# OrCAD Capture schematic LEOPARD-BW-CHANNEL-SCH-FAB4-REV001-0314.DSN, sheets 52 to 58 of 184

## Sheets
52 137_CPLD FOR LOGIC: size A3; title: CPLD FOR LOGIC
53 136_POWER CONNECTOR: size A3; title: POWER CONNECTOR
54 135_IRQ_ALERT: size A3; title: IRQ_ALERT
55 134_CKMNG 202: size A3; title: CKMNG 202
56 133_DB1900Z CLOCK TERMINATION2: size A3; title: DB1900Z CLOCK TERMINATION2
57 132_DB1900Z CLOCK TERMINATION1: size A3; title: DB1900Z CLOCK TERMINATION1
58 131_DB1900Z CLOCK BUFFER: size A3; title: DB1900Z CLOCK BUFFER

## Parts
sheet 131_DB1900Z CLOCK BUFFER
C433  SC10U6D3V5KX-4GP  [C805H58]
C434  SCD1U16V2KX-3GP  [C402H22]
C435  SCD1U16V2KX-3GP  [C402H22]
C436  SC10U6D3V5KX-4GP  [C805H58]
C437  SC10U6D3V5KX-4GP  [C805H58]
C438  SCD1U16V2KX-3GP  [C402H22]
C439  SCD1U16V2KX-3GP  [C402H22]
C440  SCD1U16V2KX-3GP  [C402H22]
C441  SCD1U16V2KX-3GP  [C402H22]
C442  SCD1U16V2KX-3GP  [C402H22]
C443  SCD1U16V2KX-3GP  [C402H22]
C444  SCD1U16V2KX-3GP  [C402H22]
C445  SCD1U16V2KX-3GP  [C402H22]
C446  SCD1U16V2KX-3GP  [C402H22]
C447  SCD1U16V2KX-3GP  [C402H22]
C448  SCD1U16V2KX-3GP  [C402H22]
C449  SCD1U16V2KX-3GP  [C402H22]
DB1  9ZX21901BKLFT-GP-U  [QFN72-G6D15-DIFF-H40]
L16  MMZ2012S601ATA1N-GP  [L805H42]
L17  BLM18SG331TN1D-GP  [L1608-UH38]
Q5  2N7002-7F-GP  [SOT23DGS2D4H44]
R442  2D2R3J-2-GP  [R603H22]
R443  1KR2F-3-GP  [R402H16]
R444  1KR2F-3-GP  [R402H16]
R445  1KR2F-L-GP  [R402H16]
R446  1KR2F-L-GP  [R402H16]
R447  2D2R3J-2-GP  [R603H22]
R448  412R2F-GP  [R402H16]
R449  4K7R2J-2-GP  [R402H16]
R450  4K7R2J-2-GP  [R402H16]
R451  4K7R2J-2-GP  [R402H16]
R452  4K7R2J-2-GP  [R402H16]
R453  4K7R2J-2-GP  [R402H16]
R454  4K7R2J-2-GP  [R402H16]
R455  0R2J-2-GP  [R402H16]
R456  4K7R2J-2-GP  [R402H16]
R457  27D4R2F-3-GP  [R402H16]
R458  27D4R2F-3-GP  [R402H16]
R459  42D2R2F-GP  [R402H16]
R460  42D2R2F-GP  [R402H16]
R496  4K7R2J-2-GP  [R402H16]
R498  4K7R2J-2-GP  [R402H16]
R653  0R2J-2-GP  [R402H16]
R1120  1KR2F-3-GP  [R402H16]
sheet 132_DB1900Z CLOCK TERMINATION1
R469  27D4R2F-3-GP  [R402H16]
R471  42D2R2F-GP  [R402H16]
R472  27D4R2F-3-GP  [R402H16]
R473  27D4R2F-3-GP  [R402H16]
R474  42D2R2F-GP  [R402H16]
R475  42D2R2F-GP  [R402H16]
R476  27D4R2F-3-GP  [R402H16]
R477  27D4R2F-3-GP  [R402H16]
R479  42D2R2F-GP  [R402H16]
R481  27D4R2F-3-GP  [R402H16]
R483  42D2R2F-GP  [R402H16]
R486  27D4R2F-3-GP  [R402H16]
R488  42D2R2F-GP  [R402H16]
R490  27D4R2F-3-GP  [R402H16]
R492  42D2R2F-GP  [R402H16]
R493  42D2R2F-GP  [R402H16]
R535  42D2R2F-GP  [R402H16]
R537  27D4R2F-3-GP  [R402H16]
R539  42D2R2F-GP  [R402H16]
R546  27D4R2F-3-GP  [R402H16]
R703  42D2R2F-GP  [R402H16]
R704  27D4R2F-3-GP  [R402H16]
R705  27D4R2F-3-GP  [R402H16]
R739  42D2R2F-GP  [R402H16]
sheet 133_DB1900Z CLOCK TERMINATION2
R501  27D4R2F-3-GP  [R402H16]
R502  27D4R2F-3-GP  [R402H16]
R503  42D2R2F-GP  [R402H16]
R504  42D2R2F-GP  [R402H16]
R505  27D4R2F-3-GP  [R402H16]
R506  27D4R2F-3-GP  [R402H16]
R507  42D2R2F-GP  [R402H16]
R508  42D2R2F-GP  [R402H16]
R510  27D4R2F-3-GP  [R402H16]
R512  42D2R2F-GP  [R402H16]
R514  27D4R2F-3-GP  [R402H16]
R516  42D2R2F-GP  [R402H16]
R517  27D4R2F-3-GP  [R402H16]
R519  42D2R2F-GP  [R402H16]
R521  27D4R2F-3-GP  [R402H16]
R523  42D2R2F-GP  [R402H16]
R525  27D4R2F-3-GP  [R402H16]
R527  42D2R2F-GP  [R402H16]
R529  27D4R2F-3-GP  [R402H16]
R531  42D2R2F-GP  [R402H16]
R735  42D2R2F-GP  [R402H16]
R736  42D2R2F-GP  [R402H16]
R737  27D4R2F-3-GP  [R402H16]
R738  27D4R2F-3-GP  [R402H16]
R758  42D2R2F-GP  [R402H16]
R759  27D4R2F-3-GP  [R402H16]
R760  42D2R2F-GP  [R402H16]
R761  27D4R2F-3-GP  [R402H16]
sheet 134_CKMNG 202
C452  SCD01U25V2KX-3GP  [C402H22]
C453  SC10U6D3V5KX-4GP  [C805H58]
C454  SC1U10V2KX-4-GP  [C402H22]
C455  SCD01U25V2KX-3GP  [C402H22]
C456  SCD1U16V2KX-3GP  [C402H22]
C457  SC1U10V2KX-4-GP  [C402H22]
C458  SCD1U16V2KX-3GP  [C402H22]
C459  SCD1U16V2KX-3GP  [C402H22]
C460  SC1U10V2KX-4-GP  [C402H22]
C461  SC1U10V2KX-4-GP  [C402H22]
C462  SC12P50V2JN-3GP  [C402H24]
C463  SC12P50V2JN-3GP  [C402H24]
L18  MMZ2012S601ATA1N-GP  [L805H42]
R201  33R2F-3-GP  [R402H16]
R541  2D2R3-1-U-GP  [R603H22]
R542  2D2R3-1-U-GP  [R603H22]
R543  4K7R2F-GP  [R402H16]
R544  4K7R2F-GP  [R402H16]
R545  4K7R2F-GP  [R402H16]
R548  22R2F-1-GP  [R402H16]
R549  1KR2F-3-GP  [R402H16]
R550  475R2F-L1-GP  [R402H16]
R551  100R2F-L1-GP-U  [R402H14]
R591  22R2F-1-GP  [R402H16]
R592  22R2F-1-GP  [R402H16]
R734  22R2F-1-GP  [R402H16]
TP299  TPAD24  [TPAD24]
TP300  TPAD24  [TPAD24]
TP439  TPAD24  [TPAD24]
U35  ICS9FGP202YKLF-GP  [QFN40-G3H40]
X5  XTAL-25MHZ-96GP  [SMD49-4H56]
sheet 135_IRQ_ALERT
C479  SCD1U16V2KX-3GP  [C402H22]
Q82  2N7002-7F-GP  [SOT23DGS2D4H44]
R804  10KR2J-3-GP  [R402H16]
R805  1KR2F-L-GP  [R402H16]
R818  0R2J-2-GP  [R402H16]
R819  1KR2F-3-GP  [R402H16]
R820  0R2J-2-GP  [R402H16]
R821  0R2J-2-GP  [R402H16]
R937  10KR2J-3-GP  [R402H16]
R1854  0R2J-2-GP  [R402H16]
sheet 136_POWER CONNECTOR
PWRCN1  TE-CONN12-2R-2-GP  [PREFIT-12P-104170H319]
PWRCN2  TE-CONN12-2R-2-GP  [PREFIT-12P-104170H319]
sheet 137_CPLD FOR LOGIC
C109  SCD1U16V2KX-3GP  [C402H22]
C405  SC1U10V2KX-4-GP  [C402H22]
C410  SC1U10V2KX-4-GP  [C402H22]
C415  SC1U10V2KX-4-GP  [C402H22]
C416  SC1U10V2KX-4-GP  [C402H22]
C417  SC1U10V2KX-4-GP  [C402H22]
C418  SC1U10V2KX-4-GP  [C402H22]
C420  SC1U10V2KX-4-GP  [C402H22]
C421  SC1U10V2KX-4-GP  [C402H22]
C422  SC1U10V2KX-4-GP  [C402H22]
C423  SC1U10V2KX-4-GP  [C402H22]
CPLD2  LCMXO256C-3MN100C-GP  [BGA100G80H54]
Q50  2N7002-7F-GP  [SOT23DGS2D4H44]
R276  100KR2F-L1-GP  [R402H16]
R388  0R2J-2-GP  [R402H16]
R405  0R2J-2-GP  [R402H16]
R424  0R2J-2-GP  [R402H16]
R430  0R2J-2-GP  [R402H16]
R433  0R2J-2-GP  [R402H16]
R435  49D9R2F-GP  [R402H16]
R436  49D9R2F-GP  [R402H16]
R437  49D9R2F-GP  [R402H16]
R438  49D9R2F-GP  [R402H16]
R439  49D9R2F-GP  [R402H16]
R441  49D9R2F-GP  [R402H16]
R461  0R2J-2-GP  [R402H16]
R485  49D9R2F-GP  [R402H16]
R495  0R2J-2-GP  [R402H16]
R497  0R2J-2-GP  [R402H16]
R513  0R2J-2-GP  [R402H16]
R526  0R2J-2-GP  [R402H16]
R534  0R2J-2-GP  [R402H16]
R536  0R2J-2-GP  [R402H16]
R607  0R2J-2-GP  [R402H16]
R613  0R2J-2-GP  [R402H16]
R642  1KR2F-3-GP  [R402H16]
R643  1KR2F-3-GP  [R402H16]
R644  10KR2F-2-GP  [R402H16]
R647  0R2J-2-GP  [R402H16]
R652  0R2J-2-GP  [R402H16]
R658  10KR2F-2-GP  [R402H16]
R659  1KR2F-3-GP  [R402H16]
R664  0R2J-2-GP  [R402H16]
R666  10KR2F-2-GP  [R402H16]
R667  4K7R2F-GP  [R402H16]
R668  10KR2J-3-GP  [R402H16]
R669  4K75R2F-1-GP  [R402H16]
R670  0R2J-2-GP  [R402H16]
R671  10KR2J-3-GP  [R402H16]
R672  10KR2J-3-GP  [R402H16]
R673  10KR2J-3-GP  [R402H16]
R686  0R2J-2-GP  [R402H16]
R688  0R2J-2-GP  [R402H16]
R770  1KR2J-1-GP  [R402H16]
R861  49D9R2F-GP  [R402H16]
R871  49D9R2F-GP  [R402H16]
R885  49D9R2F-GP  [R402H16]
R886  49D9R2F-GP  [R402H16]
R908  49D9R2F-GP  [R402H16]
R928  49D9R2F-GP  [R402H16]
R1215  49D9R2F-GP  [R402H16]
R1223  49D9R2F-GP  [R402H16]
R1224  49D9R2F-GP  [R402H16]
U24  SN74LVC1G07DCKRG4-2-GP  [SC70-5H44]

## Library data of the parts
C433 C436 C437 C453 = SC10U6D3V5KX-4GP: CHIP CAP C 10U 6.3V K0805 X7R; GREENDFACTOR: R2_SA;HF_SA;G_SA;; Part Number: 78.10620.21L; Part Type: SMD-BCG; SPEC: http://wpqssvr.wistron.com.tw:7001/wpqs/servlet/COM.qpart.Attachment?PartNumber=78.10620.21L
C434 C435 C438-C449 = SCD1U16V2KX-3GP: CHIP CAP C 0.1U 16V K0402 X7R; Category: CLK GEN; GREENDFACTOR: R_SA;HF_SA;G_SA;; Part Number: 78.10421.2FL; Quotation: 12_14; Type: SMD
DB1 = 9ZX21901BKLFT-GP-U: IC BUF 9ZX21901BKLFT MLF 72P; GREENDFACTOR: R2_SA;HF_SA;; Part Number: 71.92190.003; Part Type: ASIC-G2; SPEC: http://wpqssvr.wistron.com.tw:7001/wpqs/servlet/COM.qpart.Attachment?PartNumber=71.92190.003
L16 L18 = MMZ2012S601ATA1N-GP: CHIP BEAD MMZ2012S601ATA1N TDK; Category: Clock; DESCRIPTIO: CHIP BEAD MMZ2012S601ATA1N TDK; GREENDFACTOR: R2_SA;; Package Type: DISCRET-G5; Part Number: 68.00109.171; Part Type: DISCRET-G5; SPEC: http://wpqssvr.wistron.com.tw:7001/wpqs/servlet/COM.qpart.Attachment?PartNumber=68.00109.171; VENDORPARTNUMBER: MMZ2012S601ATA1N
L17 = BLM18SG331TN1D-GP: CHIP BEAD BLM18SG331TN1D; GREENDFACTOR: R2_SA;; Package Type: DISCRET-G2; Part Number: 68.00143.151; SPEC: http://wpqssvr.wistron.com.tw:7001/wpqs/servlet/COM.qpart.Attachment?PartNumber=68.00143.151
Q5 Q50 Q82 = 2N7002-7F-GP: FET MOS 2N7002-7-F NC SOT-23; GREENDFACTOR: R2_SA;HF_SA;G_SA;; Part Number: 84.27002.N31; Part Type: DISCRET-G; SPEC: http://wpqssvr.wistron.com.tw:7001/wpqs/servlet/COM.qpart.Attachment?PartNumber=84.27002.N31
R442 R447 = 2D2R3J-2-GP: CHIP RES 2.2 J 1/10W 0603; GREENDFACTOR: R2_SA;HF_SA;G_SA;; Package Type: SMD-RG; Part Number: 63.2R233.15L; SPEC: http://wpqssvr.wistron.com.tw:7001/wpqs/servlet/COM.qpart.Attachment?PartNumber=63.2R233.15L
R443 R444 = 1KR2F-3-GP: CHIP RES 1K F 1/16W 0402; Category: PCH; GREENDFACTOR: R2_SA;HF_SA;G_SA;; POP?: NOPOP; Package Type: SMD-RG; Part Number: 64.10015.6DL; Part Type: SMD-RG; SPEC: http://wpqssvr.wistron.com.tw:7001/wpqs/servlet/COM.qpart.Attachment?PartNumber=64.10015.6DL; VENDORPARTNUMBER: RM04FTN1001 / RTT021001FTH / RR0510S-1001-FN / RC0402FR-071KL/WR04X1001FTL
R445 R446 = 1KR2F-L-GP: CHIP RES 1K F 1/16W 0402; GREENDFACTOR: R2_SA;HF_SA;G_SA;; Package Type: SMD-RG2; Part Number: 64.10015.L1L; SPEC: http://wpqssvr.wistron.com.tw:7001/wpqs/servlet/COM.qpart.Attachment?PartNumber=64.10015.L1L
R448 = 412R2F-GP: CHIP RES 412 F 1/16W 0402; Category: Clock; DESCRIPTIO: CHIP RES 412 F 1/16W 0402; GREENDFACTOR: R2_SA;HF_SA;G_SA;; Package Type: RCL_GP; Part Number: 64.41205.6DL; Part Type: RCL_GP; SPEC: http://wpqssvr.wistron.com.tw:7001/wpqs/servlet/COM.qpart.Attachment?PartNumber=64.41205.6DL; VENDORPARTNUMBER: RM04FTN4120/RTT024120FTH/RR0510S-4120-FN/RC0402FR-07412RL
R449 R452 = 4K7R2J-2-GP: CHIP RES 4.7K J 1/16W 0402; Category: SMBUS; GREENDFACTOR: R_SA;HF_SA;G_SA;; POP?: NOPOP; Part Number: 63.47234.1DL; Quotation: 8_1; Type: SMD
R450 R451 R453 R454 R456 R496 R498 = 4K7R2J-2-GP: CHIP RES 4.7K J 1/16W 0402; Category: SMBUS; GREENDFACTOR: R_SA;HF_SA;G_SA;; Part Number: 63.47234.1DL; Quotation: 8_1; Type: SMD
R455 = 0R2J-2-GP: CHIP RES 0 J 1/16W 0402; Category: PCH; DESCRIPTIO: CHIP RES 0 J 1/16W 0402; GREENDFACTOR: R2_SA;HF_SA;G_SA;; Package Type: SMD-RG; Part Number: 63.R0034.1DL; Part Type: SMD-RG; SPEC: http://wpqssvr.wistron.com.tw:7001/wpqs/servlet/COM.qpart.Attachment?PartNumber=63.R0034.1DL; VENDORPARTNUMBER: RM04JTN0/RTT02000JTH/RR0510X-000-XN/RC0402JR-070RL/WR04X000 PTL
R457 R458 R469 R472 R473 R476 R477 R481 R486 R490 R501 R502 R505 R506 R510 R514 R517 R521 R525 R529 R537 R546 R704 R705 R737 R738 R759 R761 = 27D4R2F-3-GP: CHIP RES 27.4 F 1/16W 0402; GREENDFACTOR: R2_SA;HF_SA;G_SA;; Part Number: 64.27R45.6DL; Part Type: SMD-RG2; SPEC: http://wpqssvr.wistron.com.tw:7001/wpqs/servlet/COM.qpart.Attachment?PartNumber=64.27R45.6DL
R459 R460 R471 R474 R475 R479 R483 R488 R492 R493 R503 R504 R507 R508 R512 R516 R519 R523 R527 R531 R535 R539 R703 R735 R736 R739 R758 R760 = 42D2R2F-GP: CHIP RES 42.2 F 1/16W 0402; Category: CLOCKS; Change to: 78P0751AA; GREENDFACTOR: R2_SA;HF_SA;G_SA;; Part Number: 64.42R25.6DL; Part Type: RCL_GP; SPEC: http://wpqssvr.wistron.com.tw:7001/wpqs/servlet/COM.qpart.Attachment?PartNumber=64.42R25.6DL; Vender: TA-I/RALEC/CYNTEC/YAGEO
R653 = 0R2J-2-GP: CHIP RES 0 J 1/16W 0402; Category: LOM - i350; DESCRIPTIO: CHIP RES 0 J 1/16W 0402; GREENDFACTOR: R2_SA;HF_SA;G_SA;; Package Type: SMD-RG; Part Number: 63.R0034.1DL; Part Type: SMD-RG; SPEC: http://wpqssvr.wistron.com.tw:7001/wpqs/servlet/COM.qpart.Attachment?PartNumber=63.R0034.1DL; VENDORPARTNUMBER: RM04JTN0/RTT02000JTH/RR0510X-000-XN/RC0402JR-070RL/WR04X000 PTL
R1120 = 1KR2F-3-GP: CHIP RES 1K F 1/16W 0402; GREENDFACTOR: R2_SA;HF_SA;G_SA;; POP?: NOPOP; Part Number: 64.10015.6DL; Part Type: SMD-RG; SPEC: http://wpqssvr.wistron.com.tw:7001/wpqs/servlet/COM.qpart.Attachment?PartNumber=64.10015.6DL
C452 C455 = SCD01U25V2KX-3GP: CHIP 0.01U 25V K0402 X7R(ROHS); Category: Clock; DESCRIPTIO: CHIP 0.01U 25V K0402 X7R(ROHS); GREENDFACTOR: R2_SA;HF_SA;G_SA;; Package Type: SMD-BCG; Part Number: 78.10322.2FL; Part Type: SMD-BCG; SPEC: http://wpqssvr.wistron.com.tw:7001/wpqs/servlet/COM.qpart.Attachment?PartNumber=78.10322.2FL; VENDORPARTNUMBER: 04023C103KAT2A/C1005X7R103KFT/GRM155R71E103KA01D/223891715636/CL05B103KA5NNNC/TMK105BJ103KV-F/C1005X7R1E103KT000F
C405 C410 C415-C418 C420-C423 C454 C457 C460 C461 = SC1U10V2KX-4-GP: CHIP CAP C 1U 10V K 0402 X6S; GREENDFACTOR: R2_SA;HF_SA;; Part Number: 78.10523.8FL; Part Type: SMD-BCG6; SPEC: http://wpqssvr.wistron.com.tw:7001/wpqs/servlet/COM.qpart.Attachment?PartNumber=78.10523.8FL
C456 C458 C459 = SCD1U16V2KX-3GP: CHIP CAP C 0.1U 16V K0402 X7R; CATEGORIES: CAP_1.xV; GREENDFACTOR: R2_SA;HF_SA;G_SA;; MAIN_SOURCE: M; Part Number: 78.10421.2FL; Part Type: SMD-BCG; SPEC: http://wpqssvr.wistron.com.tw:7001/wpqs/servlet/COM.qpart.Attachment?PartNumber=78.10421.2FL
C462 C463 = SC12P50V2JN-3GP: CHIP CAP C 12P 50V J0402 NPO; CATEGORIES: CAP_Small; Category: Clock; GREENDFACTOR: R2_SA;HF_SA;G_SA;; MAIN_SOURCE: M; Package Type: SMD-BCG; Part Number: 78.12034.1FL; Part Type: SMD-BCG; SPEC: http://wpqssvr.wistron.com.tw:7001/wpqs/servlet/COM.qpart.Attachment?PartNumber=78.12034.1FL; VENDORPARTNUMBER: 04025A120JAT2A/GRM1555C1H120JZ01D/223886915129/UMK105CH120JW-F/C1005C0G1H120J/C1005NP0120JGT/GRM1555C1H120JA01D/0402N120J500
R201 = 33R2F-3-GP: CHIP RES 33 F 1/16W 0402(ROHS); GREENDFACTOR: R2_SA;HF_SA;G_SA;; Part Number: 64.33R05.6DL; Part Type: SMD-RG; SPEC: http://wpqssvr.wistron.com.tw:7001/wpqs/servlet/COM.qpart.Attachment?PartNumber=64.33R05.6DL
R541 R542 = 2D2R3-1-U-GP: CHIP RES 2.2 F 1/10W 0603(ROHS; Category: Clock; DESCRIPTIO: CHIP RES 2.2 F 1/10W 0603(ROHS; GREENDFACTOR: R2_SA;HF_SA;G_SA;; Note: Must be 1% 0603; Package Type: RCL_GP; Part Number: 64.2R205.55L; Part Type: RCL_GP; SPEC: http://wpqssvr.wistron.com.tw:7001/wpqs/servlet/COM.qpart.Attachment?PartNumber=64.2R205.55L; VENDORPARTNUMBER: RM06FTN2R20/RC0603FR-072R2/RTT032R20FTP/WR06W2R20FTL
R543 R544 = 4K7R2F-GP: CHIP RES 4.7K F 1/16W 0402; Category: CPU SIDE BAND; Part Number: 64.47015.6DL; Part Type: RCL_GP
R545 = 4K7R2F-GP: CHIP RES 4.7K F 1/16W 0402; Category: Clock; DESCRIPTIO: CHIP RES 4.7K F 1/16W 0402; GREENDFACTOR: R2_SA;HF_SA;G_SA;; Package Type: RCL_GP; Part Number: 64.47015.6DL; Part Type: RCL_GP; SPEC: http://wpqssvr.wistron.com.tw:7001/wpqs/servlet/COM.qpart.Attachment?PartNumber=64.47015.6DL; VENDORPARTNUMBER: RM04FTN4701/RTT024701FTH/RR0510S-472-FN/RC0402FR-074K7L/WR04X4701FTL
R548 R591 R592 R734 = 22R2F-1-GP: CHIP RES 22 F 1/16W 0402(ROHS); Category: Clock; DESCRIPTIO: CHIP RES 22 F 1/16W 0402(ROHS); GREENDFACTOR: R2_SA;HF_SA;G_SA;; Package Type: SMD-RG; Part Number: 64.22R05.6DL; Part Type: SMD-RG; SPEC: http://wpqssvr.wistron.com.tw:7001/wpqs/servlet/COM.qpart.Attachment?PartNumber=64.22R05.6DL; VENDORPARTNUMBER: RM04FTN22R0/RTT0222R0FTH/RR0510S-220-FN/RC0402FR-0722RL
R549 = 1KR2F-3-GP: CHIP RES 1K F 1/16W 0402; Category: Clock; DESCRIPTIO: CHIP RES 1K F 1/16W 0402; GREENDFACTOR: R2_SA;HF_SA;G_SA;; Package Type: SMD-RG; Part Number: 64.10015.6DL; Part Type: SMD-RG; SPEC: http://wpqssvr.wistron.com.tw:7001/wpqs/servlet/COM.qpart.Attachment?PartNumber=64.10015.6DL; VENDORPARTNUMBER: RM04FTN1001 / RTT021001FTH / RR0510S-1001-FN / RC0402FR-071KL/WR04X1001FTL
R550 = 475R2F-L1-GP: CHIP RES 475 F 1/16W 0402; Category: Clock; DESCRIPTIO: CHIP RES 475 F 1/16W 0402; GREENDFACTOR: R2_SA;HF_SA;G_SA;; Package Type: SMD-RG; Part Number: 64.47505.6DL; Part Type: SMD-RG; SPEC: http://wpqssvr.wistron.com.tw:7001/wpqs/servlet/COM.qpart.Attachment?PartNumber=64.47505.6DL; VENDORPARTNUMBER: RM04FTN4750 / RTT024750FTH / RR0510S-4750-FN / RC0402FR-07475RL/WR04X4750FTL
R551 = 100R2F-L1-GP-U: CHIP RES 100 F 1/16W 0402; Category: Clock; DESCRIPTIO: CHIP RES 100 F 1/16W 0402; GREENDFACTOR: R2_SA;HF_SA;G_SA;; Package Type: SMD-RG; Part Number: 64.10005.6DL; Part Type: SMD-RG; SPEC: http://wpqssvr.wistron.com.tw:7001/wpqs/servlet/COM.qpart.Attachment?PartNumber=64.10005.6DL; VENDORPARTNUMBER: RM04FTN1000 / RTT021000FTH / RR0510S-1000-FN / RC0402FR-07100RL/WR04X1000FTL
TP299 TP300 TP439 = TPAD24: 24 MILS TEST PAD; Part Number: ZZ.PAD24.001; Part Type: DISCRET2
U35 = ICS9FGP202YKLF-GP: IC CLK ICS9FGP202AKLF MLF 41P; Category: Clock; DESCRIPTIO: IC CLK ICS9FGP202AKLF MLF 41P; GREENDFACTOR: R2_SA;HF_SA;; Note: The same as L82TT1; Package Type: ASIC-G1; Part Number: 71.09202.003; Part Type: ASIC-G1; SPEC: http://wpqssvr.wistron.com.tw:7001/wpqs/servlet/COM.qpart.Attachment?PartNumber=71.09202.003; VENDORPARTNUMBER: ICS9FGP202AKLFT
X5 = XTAL-25MHZ-96GP: XTAL 25MHZ 12P X5H025000FC1H-H; GREENDFACTOR: R2_SA;HF_SA;G_SA;; Package Type: DISCRET-G1; Part Number: 82.30020.791; SPEC: http://wpqssvr.wistron.com.tw:7001/wpqs/servlet/COM.qpart.Attachment?PartNumber=82.30020.791
C479 = SCD1U16V2KX-3GP: CHIP CAP C 0.1U 16V K0402 X7R; CATEGORIES: CAP_1.xV; GREENDFACTOR: R2_SA;HF_SA;G_SA;; MAIN_SOURCE: M; POP?: NOPOP; Part Number: 78.10421.2FL; Part Type: SMD-BCG; SPEC: http://wpqssvr.wistron.com.tw:7001/wpqs/servlet/COM.qpart.Attachment?PartNumber=78.10421.2FL
R668 R671-R673 R804 = 10KR2J-3-GP: CHIP RES 10K J 1/16W 0402; Category: PWRI/O CONN; GREENDFACTOR: R2_SA;HF_SA;G_SA;; Module: Internal Connector; Package Type: SMD-RG; Part Number: 63.10334.1DL; SPEC: http://wpqssvr.wistron.com.tw:7001/wpqs/servlet/COM.qpart.Attachment?PartNumber=63.10334.1DL
R805 = 1KR2F-L-GP: CHIP RES 1K F 1/16W 0402; GREENDFACTOR: R2_SA;HF_SA;G_SA;; Part Number: 64.10015.L1L; Part Type: SMD-RG2; SPEC: http://wpqssvr.wistron.com.tw:7001/wpqs/servlet/COM.qpart.Attachment?PartNumber=64.10015.L1L
R534 R536 R818 = 0R2J-2-GP: CHIP RES 0 J 1/16W 0402; Belong: POP; Category: PWRI/O CONN; GREENDFACTOR: R2_SA;HF_SA;G_SA;; POP?: NOPOP; Part Number: 63.R0034.1DL; Part Type: SMD-RG; SPEC: http://wpqssvr.wistron.com.tw:7001/wpqs/servlet/COM.qpart.Attachment?PartNumber=63.R0034.1DL
R819 = 1KR2F-3-GP: CHIP RES 1K F 1/16W 0402; Category: PCH; GREENDFACTOR: R2_SA;HF_SA;G_SA;; Package Type: SMD-RG; Part Number: 64.10015.6DL; Part Type: SMD-RG; SPEC: http://wpqssvr.wistron.com.tw:7001/wpqs/servlet/COM.qpart.Attachment?PartNumber=64.10015.6DL; VENDORPARTNUMBER: RM04FTN1001 / RTT021001FTH / RR0510S-1001-FN / RC0402FR-071KL/WR04X1001FTL
R388 R405 R424 R430 R495 R497 R513 R526 R607 R613 R820 R821 R1854 = 0R2J-2-GP: CHIP RES 0 J 1/16W 0402; Belong: POP; Category: PWRI/O CONN; GREENDFACTOR: R2_SA;HF_SA;G_SA;; Part Number: 63.R0034.1DL; Part Type: SMD-RG; SPEC: http://wpqssvr.wistron.com.tw:7001/wpqs/servlet/COM.qpart.Attachment?PartNumber=63.R0034.1DL
R937 = 10KR2J-3-GP: CHIP RES 10K J 1/16W 0402; Category: PWRI/O CONN; GREENDFACTOR: R2_SA;HF_SA;G_SA;; Module: Internal Connector; POP?: NOPOP; Package Type: SMD-RG; Part Number: 63.10334.1DL; SPEC: http://wpqssvr.wistron.com.tw:7001/wpqs/servlet/COM.qpart.Attachment?PartNumber=63.10334.1DL
PWRCN1 = TE-CONN12-2R-2-GP: C.A. PRESSFIT CABLE WITH SCREW; GREENDFACTOR: R2_C;; POP?: NOPOP; Part Number: B50.00K01.0001; Part Type: CONN-G4; SPEC: http://wpqssvr.wistron.com.tw:7001/wpqs/servlet/COM.qpart.Attachment?PartNumber=B50.00K01.0001
PWRCN2 = TE-CONN12-2R-2-GP: C.A. PRESSFIT CABLE WITH SCREW; GREENDFACTOR: R2_C;; Part Number: B50.00K01.0001; Part Type: CONN-G4; SPEC: http://wpqssvr.wistron.com.tw:7001/wpqs/servlet/COM.qpart.Attachment?PartNumber=B50.00K01.0001
C109 = SCD1U16V2KX-3GP: CHIP CAP C 0.1U 16V K0402 X7R; Category: CLK GEN; GREENDFACTOR: R_SA;HF_SA;G_SA;; Part Number: 78.10421.2FL; Quotation: 13_8; Type: SMD
CPLD2 = LCMXO256C-3MN100C-GP: IC CPLD LCMXO256C-3MN100C CSBGA 100P; Part Number: 73.00256.0VU; Part Type: ASIC-G3
R276 = 100KR2F-L1-GP: CHIP RES 100K F 1/16W 0402; GREENDFACTOR: R2_SA;HF_SA;G_SA;; Part Number: 64.10035.6DL; Part Type: SMD-RG; SPEC: http://wpqssvr.wistron.com.tw:7001/wpqs/servlet/COM.qpart.Attachment?PartNumber=64.10035.6DL
R433 R461 R652 R664 R670 R686 R688 = 0R2J-2-GP: CHIP RES 0 J 1/16W 0402; Category: BMC; DESCRIPTIO: CHIP RES 0 J 1/16W 0402; GREENDFACTOR: R2_SA;HF_SA;G_SA;; Package Type: SMD-RG; Part Number: 63.R0034.1DL; Part Type: SMD-RG; SPEC: http://wpqssvr.wistron.com.tw:7001/wpqs/servlet/COM.qpart.Attachment?PartNumber=63.R0034.1DL; VENDORPARTNUMBER: RM04JTN0/RTT02000JTH/RR0510X-000-XN/RC0402JR-070RL/WR04X000 PTL
R435-R439 R441 R485 R861 R871 R885 R886 R908 R928 R1215 R1223 R1224 = 49D9R2F-GP: CHIP RES 49.9 F 1/16W 0402; GREENDFACTOR: R2_SA;HF_SA;G_SA;; Part Number: 64.49R95.6DL; Part Type: RCL_GP; SPEC: http://wpqssvr.wistron.com.tw:7001/wpqs/servlet/COM.qpart.Attachment?PartNumber=64.49R95.6DL
R642 R659 = 1KR2F-3-GP: CHIP RES 1K F 1/16W 0402; Category: internal conn; GREENDFACTOR: R2_SA;HF_SA;G_SA;; POP?: NOPOP; Package Type: SMD-RG; Part Number: 64.10015.6DL; Part Type: SMD-RG; SPEC: http://wpqssvr.wistron.com.tw:7001/wpqs/servlet/COM.qpart.Attachment?PartNumber=64.10015.6DL; VENDORPARTNUMBER: RM04FTN1001 / RTT021001FTH / RR0510S-1001-FN / RC0402FR-071KL/WR04X1001FTL
R643 = 1KR2F-3-GP: CHIP RES 1K F 1/16W 0402; Category: internal conn; GREENDFACTOR: R2_SA;HF_SA;G_SA;; Package Type: SMD-RG; Part Number: 64.10015.6DL; Part Type: SMD-RG; SPEC: http://wpqssvr.wistron.com.tw:7001/wpqs/servlet/COM.qpart.Attachment?PartNumber=64.10015.6DL; VENDORPARTNUMBER: RM04FTN1001 / RTT021001FTH / RR0510S-1001-FN / RC0402FR-071KL/WR04X1001FTL
R644 = 10KR2F-2-GP: CHIP RES 10K F 1/16W 0402; Category: MSIC; DESCRIPTIO: CHIP RES 10K F 1/16W 0402; GREENDFACTOR: R2_SA;HF_SA;G_SA;; POP?: NOPOP; Package Type: SMD-RG; Part Number: 64.10025.6DL; Part Type: SMD-RG; SPEC: http://wpqssvr.wistron.com.tw:7001/wpqs/servlet/COM.qpart.Attachment?PartNumber=64.10025.6DL; VENDORPARTNUMBER: RM04FTN1002 / RTT021002FTH / RR0510S-103-FN / RC0402FR-0710KL/WR04X1002FTL
R647 = 0R2J-2-GP: CHIP RES 0 J 1/16W 0402; Category: BMC; DESCRIPTIO: CHIP RES 0 J 1/16W 0402; GREENDFACTOR: R2_SA;HF_SA;G_SA;; POP?: NOPOP; Package Type: SMD-RG; Part Number: 63.R0034.1DL; Part Type: SMD-RG; SPEC: http://wpqssvr.wistron.com.tw:7001/wpqs/servlet/COM.qpart.Attachment?PartNumber=63.R0034.1DL; VENDORPARTNUMBER: RM04JTN0/RTT02000JTH/RR0510X-000-XN/RC0402JR-070RL/WR04X000 PTL
R658 = 10KR2F-2-GP: CHIP RES 10K F 1/16W 0402; Category: MSIC; DESCRIPTIO: CHIP RES 10K F 1/16W 0402; GREENDFACTOR: R2_SA;HF_SA;G_SA;; Package Type: SMD-RG; Part Number: 64.10025.6DL; Part Type: SMD-RG; SPEC: http://wpqssvr.wistron.com.tw:7001/wpqs/servlet/COM.qpart.Attachment?PartNumber=64.10025.6DL; VENDORPARTNUMBER: RM04FTN1002 / RTT021002FTH / RR0510S-103-FN / RC0402FR-0710KL/WR04X1002FTL
R666 = 10KR2F-2-GP: CHIP RES 10K F 1/16W 0402; Category: internal conn; DESCRIPTIO: CHIP RES 10K F 1/16W 0402; GREENDFACTOR: R2_SA;HF_SA;G_SA;; Package Type: SMD-RG; Part Number: 64.10025.6DL; Part Type: SMD-RG; SPEC: http://wpqssvr.wistron.com.tw:7001/wpqs/servlet/COM.qpart.Attachment?PartNumber=64.10025.6DL; VENDORPARTNUMBER: RM04FTN1002 / RTT021002FTH / RR0510S-103-FN / RC0402FR-0710KL/WR04X1002FTL
R667 = 4K7R2F-GP: CHIP RES 4.7K F 1/16W 0402; GREENDFACTOR: R2_SA;HF_SA;G_SA;; POP?: NOPOP; Part Number: 64.47015.6DL; Part Type: RCL_GP; SPEC: http://wpqssvr.wistron.com.tw:7001/wpqs/servlet/COM.qpart.Attachment?PartNumber=64.47015.6DL
R669 = 4K75R2F-1-GP: CHIP RES 4.75K F 1/16W 0402; Category: VR_DDR; GREENDFACTOR: R2_SA;HF_SA;G_SA;; Package Type: RCL_GP; Part Number: 64.47515.6DL; Part Type: RCL_GP; SPEC: http://wpqssvr.wistron.com.tw:7001/wpqs/servlet/COM.qpart.Attachment?PartNumber=64.47515.6DL; VENDORPARTNUMBER: RM04FTN4751/RTT024751FTH/RR0510S-4751-FN/RC0402FR-074K75L
R770 = 1KR2J-1-GP: CHIP RES 1K J 1/16W 0402; GREENDFACTOR: R2_SA;HF_SA;G_SA;; Part Number: 63.10234.1DL; Part Type: SMD-RG; SPEC: http://wpqssvr.wistron.com.tw:7001/wpqs/servlet/COM.qpart.Attachment?PartNumber=63.10234.1DL
U24 = SN74LVC1G07DCKRG4-2-GP: IC BUF SN74LVC1G07DCKRG4 DCK5P; GREENDFACTOR: R2_SA;; Part Number: 73.01G07.01H; Part Type: TTL-G6; SPEC: http://wpqssvr.wistron.com.tw:7001/wpqs/servlet/COM.qpart.Attachment?PartNumber=73.01G07.01H

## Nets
GND: C109.2 C405.2 C410.2 C415.2 C416.2 C417.2 C418.2 C420.2 C421.2 C422.2 C423.2 C433.2 C434.2 C435.2 C436.2 C437.2 C438.2 C439.2 C440.2 C441.2 C442.2 C443.2 C444.2 C445.2 C446.2 C447.2 C448.2 C449.2 C452.2 C453.2 C454.2 C455.2 C456.2 C457.2 C458.2 C459.2 C460.2 C461.2 C462.2 C463.2 C479.2 CPLD2.A4(GNDIO0) CPLD2.B4(PT3A) CPLD2.B9(GND) CPLD2.B13(GNDIO0) CPLD2.C13(PR3B) CPLD2.G14(GNDIO0) CPLD2.H1(GNDIO1) CPLD2.N2(GNDIO1) CPLD2.N3(PB2B) CPLD2.N9(GND) CPLD2.N10(GNDIO1) DB1.2(GNDA) DB1.7(GND) DB1.26(GND) DB1.44(GND) DB1.63(GND) DB1.73(TH_PAD) PWRCN1.2_1 PWRCN1.2_2 PWRCN1.2_3 PWRCN1.2_4 PWRCN1.2_5 PWRCN1.2_6 PWRCN1.PTH1 PWRCN2.2_1 PWRCN2.2_2 PWRCN2.2_3 PWRCN2.2_4 PWRCN2.2_5 PWRCN2.2_6 PWRCN2.PTH1 Q5.S Q50.S R276.1 R445.2 R446.2 R448.1 R451.2 R452.2 R454.2 R459.2 R460.2 R471.2 R474.2 R475.2 R479.2 R483.2 R488.2 R492.2 R493.2 R503.2 R504.2 R507.2 R508.2 R512.2 R516.2 R519.2 R523.2 R527.2 R531.2 R535.2 R539.2 R549.2 R550.2 R642.2 R643.2 R659.2 R666.2 R669.2 R703.2 R735.2 R736.2 R739.2 R758.2 R760.2 R770.2 R1120.1 U24.3(GND) U35.1(GND) U35.10(GNDCPU) U35.14(GND32K) U35.18(GNDREF) U35.21(GND33) U35.27(GNDRMII) U35.35(GNDRMII) U35.41(GND) ; also on sheet 1 2 3 4 5 6 7 8 9 10 11 12 13 14 15 16 17 18 19 20 21 22 23 24 25 26 27 28 29 30 31 32 33 34 35 36 37 38 39 44 46 47 49 50 51 59 60 61 62 63 64 65 66 69 70 71 73 74 75 76 78 79 80 81 82 83 84 86 87 88 89 90 91 92 93 94 95 96 97 98 99 100 101 102 103 104 105 106 107 108 109 110 111 112 113 114 115 116 117 118 119 128 129 138 139 159 160 161 166 168 169 170 171 172 173 174 175 176 177 180 181 182 183 184
P3V3: C109.1 L16.1(F) L17.1 R453.1 R456.1 R496.2 R498.2 R805.1 R819.2 U24.5(VCC) ; also on sheet 1 3 8 45 46 48 49 65 74 76 78 83 84 87 90 91 94 95 96 100 101 102 161 166 168 173 174 177 180 181 182 183
P3V3_DB1900_VDDA: L16.2(S) R442.1 R447.1
P3V3_STBY: C405.1 C410.1 C415.1 C416.1 C417.1 C418.1 C420.1 C421.1 C422.1 C423.1 C460.1 CPLD2.A14(VCCIO0) CPLD2.B5(VCCIO0) CPLD2.B6(VCC) CPLD2.B7(VCCAUX) CPLD2.G1(VCCIO1) CPLD2.H14(VCCIO0) CPLD2.P1(VCCIO1) CPLD2.P7(VCC) CPLD2.P10(VCCIO1) L18.1(F) R543.1 R544.1 R644.1 R658.1 R668.1 R671.1 R672.1 R673.1 R804.1 R937.1 ; also on sheet 2 3 5 6 8 9 10 11 12 15 16 17 20 21 22 25 26 27 30 31 33 34 35 37 38 39 45 47 49 50 51 59 60 61 62 63 64 65 66 69 70 71 72 73 74 76 79 83 84 87 88 89 90 91 92 93 94 95 96 97 98 99 159 161 166 168 173 174 176 177 179 180 182 183 184
P3V3_STBY_MNG: C453.1 C456.1 C458.1 C459.1 L18.2(S) R541.1 R542.1 R545.1 U35.2(VDD96) U35.12(VDD32K) U35.15(VDDREF) U35.23(VDD33)
P3V3_STBY_MNG_IOH: C452.1 C454.1 R541.2 U35.9(VDDCPU)
P3V3_STBY_MNG_RMII: C455.1 C457.1 R542.2 U35.26(VDDRMII) U35.34(VDDRMII)
P12V_MAIN: PWRCN1.1_1 PWRCN1.1_2 PWRCN1.1_3 PWRCN1.1_4 PWRCN1.1_5 PWRCN1.1_6 PWRCN2.1_1 PWRCN2.1_2 PWRCN2.1_3 PWRCN2.1_4 PWRCN2.1_5 PWRCN2.1_6 ; also on sheet 60 93
PVCCIN_CPU0_PWRGD_R: Q5.G R455.2
PVDDQ_AB: R667.1 ; also on sheet 28 30 45 97 116 117 118 119 130 139
VDD_DB1900: C437.1 C438.1 C439.1 C440.1 C441.1 C442.1 C443.1 C444.1 C445.1 C446.1 C447.1 C448.1 C449.1 DB1.21(VDD) DB1.31(VDD) DB1.45(VDD) DB1.58(VDD) DB1.68(VDD) L17.2 R443.1 R444.1 R449.1 R450.1
VDDA_DB1900: C435.1 C436.1 DB1.1(VDDA) R447.2
VDDR_DB1900: C433.1 C434.1 DB1.8(VDD) R442.2
BMC_CURRENT_EN: R613.2 ; also on sheet 177
BMC_CURRENT_EN_CPLD: CPLD2.L13(PR8B) R613.1
CH_SELECT0: CPLD2.G2(PL5B) ; also on sheet 70
CH_SELECT1: CPLD2.H2(PL5C) ; also on sheet 70
CLK_25M_CPLD: CPLD2.B8(PT4A) R201.2
CLK_25M_CPLD_R: R201.1 U35.16(25MHZ_0)
CLK_32K_SUSCLK_PLD: U35.13(32_768KHZ) ; also on sheet 50
CLK_33M_CPLD_LPC: CPLD2.N8(PB3C) ; also on sheet 88
CLK_50M_BMC_MAC1: R591.2 ; also on sheet 180
CLK_50M_BMC_MAC1_R: R591.1 U35.33(RMII2)
CLK_50M_BMC_MAC2: R592.2 ; also on sheet 180
CLK_50M_BMC_MAC2_R: R592.1 U35.36(RMII1)
CLK_50M_BMC_NCSI: R548.2 ; also on sheet 95
CLK_50M_BMC_NCSI_R: R548.1 U35.37(RMII0)
CLK_50M_NIC: R734.2 ; also on sheet 64
CLK_50M_NIC_R: R734.1 U35.32(RMII3)
CLK_100M_CPU0_BCLK0_DN: R514.2 R516.1 ; also on sheet 139
CLK_100M_CPU0_BCLK0_DP: R510.2 R512.1 ; also on sheet 139
CLK_100M_CPU0_BCLK0_R_DN: DB1.33(DIF_5#) R514.1
CLK_100M_CPU0_BCLK0_R_DP: DB1.32(DIF_5) R510.1
CLK_100M_CPU0_BCLK1_DN: R506.2 R508.1 ; also on sheet 139
CLK_100M_CPU0_BCLK1_DP: R502.2 R504.1 ; also on sheet 139
CLK_100M_CPU0_BCLK1_R_DN: DB1.36(DIF_6#) R506.1
CLK_100M_CPU0_BCLK1_R_DP: DB1.35(DIF_6) R502.1
CLK_100M_CPU1_BCLK0_DN: R521.2 R523.1 ; also on sheet 129
CLK_100M_CPU1_BCLK0_DP: R517.2 R519.1 ; also on sheet 129
CLK_100M_CPU1_BCLK0_R_DN: DB1.39(DIF_7#) R521.1
CLK_100M_CPU1_BCLK0_R_DP: DB1.38(DIF_7) R517.1
CLK_100M_CPU1_BCLK1_DN: R529.2 R531.1 ; also on sheet 129
CLK_100M_CPU1_BCLK1_DP: R525.2 R527.1 ; also on sheet 129
CLK_100M_CPU1_BCLK1_R_DN: DB1.42(DIF_8#) R529.1
CLK_100M_CPU1_BCLK1_R_DP: DB1.41(DIF_8) R525.1
CLK_100M_DB1900_DN: DB1.10(DIF_IN#) ; also on sheet 88
CLK_100M_DB1900_DP: DB1.9(DIF_IN) ; also on sheet 88
CLK_100M_DB1900_PCH_CPY_R_DN: DB1.72(DIF_18#) R505.1
CLK_100M_DB1900_PCH_CPY_R_DP: DB1.71(DIF_18) R501.1
CLK_100M_DB1900Z_FB_DN: DB1.17(DFB_OUT#) R457.2
CLK_100M_DB1900Z_FB_DP: DB1.18(DFB_OUT) R458.2
CLK_100M_DB1900Z_FB_R_DN: DB1.16(DFB_IN#) R457.1 R459.1
CLK_100M_DB1900Z_FB_R_DP: DB1.15(DFB_IN) R458.1 R460.1
CLK_100M_MEZZ1_DN: R474.1 R476.2 ; also on sheet 95
CLK_100M_MEZZ1_DP: R472.2 R493.1 ; also on sheet 95
CLK_100M_MEZZ1_R_DN: DB1.28(DIF_3#) R476.1
CLK_100M_MEZZ1_R_DP: DB1.27(DIF_3) R472.1
CLK_100M_MEZZ2_DN: R535.1 R537.2 ; also on sheet 95
CLK_100M_MEZZ2_DP: R539.1 R546.2 ; also on sheet 95
CLK_100M_MEZZ2_R_DN: DB1.30(DIF_4#) R537.1
CLK_100M_MEZZ2_R_DP: DB1.29(DIF_4) R546.1
CLK_100M_NIC_PE_DN: R735.1 R738.2 ; also on sheet 64
CLK_100M_NIC_PE_DP: R736.1 R737.2 ; also on sheet 64
CLK_100M_NIC_PE_R_DN: DB1.65(DIF_15#) R738.1
CLK_100M_NIC_PE_R_DP: DB1.64(DIF_15) R737.1
CLK_100M_PCH_CPY_DN: R505.2 R507.1 ; also on sheet 88
CLK_100M_PCH_CPY_DP: R501.2 R503.1 ; also on sheet 88
CLK_100M_PE_D_DN: R760.1 R761.2 ; also on sheet 83
CLK_100M_PE_D_DP: R758.1 R759.2 ; also on sheet 83
CLK_100M_PE_D_R_DN: DB1.62(DIF_14#) R761.1
CLK_100M_PE_D_R_DP: DB1.61(DIF_14) R759.1
CLK_100M_RISER1_PE1_DN: R473.2 R475.1 ; also on sheet 94
CLK_100M_RISER1_PE1_DP: R469.2 R471.1 ; also on sheet 94
CLK_100M_RISER1_PE1_R_DN: DB1.23(DIF_1#) R473.1
CLK_100M_RISER1_PE1_R_DP: DB1.22(DIF_1) R469.1
CLK_100M_RISER1_PE2_DN: R481.2 R483.1 ; also on sheet 94
CLK_100M_RISER1_PE2_DP: R477.2 R479.1 ; also on sheet 94
CLK_100M_RISER1_PE2_R_DN: DB1.25(DIF_2#) R481.1
CLK_100M_RISER1_PE2_R_DP: DB1.24(DIF_2) R477.1
CLK_100M_RISER1_PE3_DN: R705.2 R739.1 ; also on sheet 94
CLK_100M_RISER1_PE3_DP: R703.1 R704.2 ; also on sheet 94
CLK_100M_RISER1_PE3_R_DN: DB1.53(DIF_11#) R705.1
CLK_100M_RISER1_PE3_R_DP: DB1.52(DIF_11) R704.1
CLK_100M_RISER2_PE1_DN: R490.2 R492.1 ; also on sheet 93
CLK_100M_RISER2_PE1_DP: R486.2 R488.1 ; also on sheet 93
CLK_100M_RISER2_PE1_R_DN: DB1.56(DIF_12#) R490.1
CLK_100M_RISER2_PE1_R_DP: DB1.55(DIF_12) R486.1
CLK_COMP_CKMNG: R550.1 U35.11(IREF)
CLK_COMP_DB1900Z: DB1.3(IREF) R448.2
CPLD2_OK_HB: CPLD2.A6(PT3C) ; also on sheet 177
CPLD_ID: CPLD2.A2(PT2D) R643.1
CPLD_LED_CATERR: R670.2 R673.2 ; also on sheet 76
CPLD_LED_CATERR_R: CPLD2.A10(PT4E) R670.1
CURRENT_ALERT_CPLD_OUT: CPLD2.E13(PR4B) R647.1
CURRENT_ALERT_N: CPLD2.C14(PR3C) ; also on sheet 61
DB1_OE9_N: DB1.48(OE9#) R496.1
DB1_OE10_N: DB1.51(OE10#) R498.1
FAN0_PWM_BMC: CPLD2.N6(PB2D) ; also on sheet 66 177
FAN1_PWM_BMC: CPLD2.N7(PB3A) ; also on sheet 66 177
FM_ADR_BMC_TRIGGER: CPLD2.M3(PL9A) ; also on sheet 177
FM_ADR_COMPLETE_CPLD_SAVE: R686.1 ; also on sheet 51
FM_ADR_COMPLETE_SAVE: Q50.G R666.1 R686.2
FM_ADR_COMPLETE_SAVE_N: Q50.D R276.2 R435.1 R436.1 R437.1 R438.1 R439.1 R441.1 R485.1 R664.2 R667.2 R861.1 R871.1 R885.1 R886.1 R908.1 R928.1 R1215.1 R1223.1 R1224.1
FM_ADR_COMPLETE_SAVE_R_N: R664.1 U24.2(A)
FM_ADR_TRIGGER_EN: CPLD2.P3(PL9B) ; also on sheet 177
FM_ADR_TRIGGER_N: CPLD2.A7(PT3D) R821.1
FM_BMC_READY_N: CPLD2.F1(PL4B) ; also on sheet 51 74 166
FM_CPLD_BMC_THERMTRIP_N: CPLD2.N11(PB4B) ; also on sheet 180
FM_CPLD_PCH_CATERR_MSMI_N: CPLD2.B12(PT4F) R672.2 ; also on sheet 100
FM_CPU_CATERR_LVT3_N: CPLD2.B10(PT4D) ; also on sheet 74 101
FM_CPU_MSMI_LVT3_BMC_N: CPLD2.A9(PT4C) ; also on sheet 101 177
FM_GPIO_ALERT_BUF_EN: R461.2 ; also on sheet 91
FM_GPIO_ALERT_BUF_PLD: CPLD2.G13(PR5D) R461.1
FM_PCH_BMC_THERMTRIP_N: CPLD2.P9(PB3D) ; also on sheet 90
FM_PLD_CLK_EN: R653.1 R1120.2 ; also on sheet 51
FM_PMBUS_ALERT_BUF_EN: R433.2 R770.1 ; also on sheet 84 166
FM_PMBUS_ALERT_BUF_PLD: CPLD2.F14(PR5C) R433.1
FM_SLPS3_N: R497.2 ; also on sheet 51 59 74 90
FM_SLPS3_N_CPLD: CPLD2.N14(PR9B) R497.1
HIGH_HEX_0: CPLD2.L2(PL7C) ; also on sheet 69
HIGH_HEX_1: CPLD2.M1(PL7D) ; also on sheet 69
HIGH_HEX_2: CPLD2.M2(PL8A) ; also on sheet 69
HIGH_HEX_3: CPLD2.N1(PL8B) ; also on sheet 69
IRQ_MID_PMBUS_ALERT_N: R1854.1 ; also on sheet 93
IRQ_SERIAL: CPLD2.C2(PL3C) ; also on sheet 74 78 91
IRQ_SML1_PMBUS_ALERT_BUF_N: R647.2 R668.2 R688.2 ; also on sheet 51 183
IRQ_SML1_PMBUS_ALERT_N: R424.2 R937.2 R1854.2 ; also on sheet 60 74 90
IRQ_SML1_PMBUS_ALERT_N_PLD: CPLD2.F13(PR5B) R424.1
JTAG_PLD1_TCK: CPLD2.N4(TCK) R669.1 ; also on sheet 50
JTAG_PLD1_TDI: CPLD2.P6(TDI) ; also on sheet 50
JTAG_PLD1_TDO: CPLD2.P5(TDO) ; also on sheet 50
JTAG_PLD1_TMS: CPLD2.P2(TMS) ; also on sheet 50
LOW_HEX_0: CPLD2.J2(PL6A) ; also on sheet 69
LOW_HEX_1: CPLD2.K1(PL6B) ; also on sheet 69
LOW_HEX_2: CPLD2.K2(PL7A) ; also on sheet 69
LOW_HEX_3: CPLD2.L1(PL7B) ; also on sheet 69
LPC_FRAME_N: CPLD2.E1(PL3D) ; also on sheet 74 78 90
NV_SAVE_CHA_DIMM0: R871.2 ; also on sheet 119
NV_SAVE_CHA_DIMM1: R435.2 ; also on sheet 118
NV_SAVE_CHB_DIMM0: R885.2 ; also on sheet 117
NV_SAVE_CHB_DIMM1: R436.2 ; also on sheet 116
NV_SAVE_CHC_DIMM0: R886.2 ; also on sheet 115
NV_SAVE_CHC_DIMM1: R437.2 ; also on sheet 114
NV_SAVE_CHD_DIMM0: R908.2 ; also on sheet 113
NV_SAVE_CHD_DIMM1: R438.2 ; also on sheet 112
NV_SAVE_CHE_DIMM0: R928.2 ; also on sheet 111
NV_SAVE_CHE_DIMM1: R439.2 ; also on sheet 110
NV_SAVE_CHF_DIMM0: R1215.2 ; also on sheet 109
NV_SAVE_CHF_DIMM1: R441.2 ; also on sheet 108
NV_SAVE_CHG_DIMM0: R1223.2 ; also on sheet 107
NV_SAVE_CHG_DIMM1: R485.2 ; also on sheet 106
NV_SAVE_CHH_DIMM0: R1224.2 ; also on sheet 105
NV_SAVE_CHH_DIMM1: R861.2 ; also on sheet 104
PCH_DIMM_RDY: U24.4(Y) ; also on sheet 91
PD_CKMNG_OE_N: R549.1 U35.5(OE_96) U35.6(OE_CPU)
PD_CLK_OE_EN_L: DB1.54(OE11#) DB1.57(OE12#) R454.1
PD_DB1900Z_SMB_SA0: DB1.11(SMB_A0_TRI) R443.2 R446.1
PD_DB1900Z_SMB_SA1: DB1.14(SMB_A1_TRI) R444.2 R445.1
PMBUS_ALERT_CPLD_OUT: CPLD2.B14(PR3A) R688.1
POWER_FAIL: R805.2 R820.2 ; also on sheet 60 91
POWER_FAIL_1_R: Q82.D R804.2 R818.2 R821.2 ; also on sheet 48
POWER_FAIL_CPLD: CPLD2.A13(PR2A) R607.1
POWER_FAIL_N: R607.2 R818.1 ; also on sheet 48 61 93 177
PU_CKMNG_OE: C461.1 R545.2 U35.30(OE_RMIIB) U35.31(OE_RMIIA)
PU_DB1900Z_100M: DB1.4(100M_133M#) R450.2 R452.1
PU_DB1900Z_HI_BW: DB1.5(HIBW_BYPM_LOBW#) R449.2 R451.1
PU_PLD1_SLEEP_N: CPLD2.M12(SLEEP#) R658.2 R659.1
PWRGD_CK_MNG_PWRDWN_N: R551.2 U35.40(VTTPWR_GD/PD#)
PWRGD_DB1900Z: DB1.6(CK_PWRGD_PD#) R456.2 R653.2
PWRGD_P3V3_AUX: R551.1 ; also on sheet 2 7
PWRGD_PCH_PWROK: R526.2 R536.1 ; also on sheet 51 90 174
PWRGD_PCH_PWROK_BMC: R495.2 R536.2 ; also on sheet 74
PWRGD_PCH_PWROK_IN: CPLD2.K14(PR7C) R526.1
PWRGD_PCH_PWROK_OUT: CPLD2.L14(PR8A) R495.1
PWRGD_PVCCIN_CPU0: R455.1 ; also on sheet 39 51
PWRGD_PVTT_CPU0_CLK_OE_N: DB1.34(OE5#) DB1.37(OE6#) DB1.40(OE7#) DB1.43(OE8#) Q5.D R453.2
PWRGD_SYS_PWROK: R513.2 R534.1 ; also on sheet 51 90 174
PWRGD_SYS_PWROK_BMC: R430.2 R534.2 ; also on sheet 74
PWRGD_SYS_PWROK_IN: CPLD2.M14(PR9A) R513.1
PWRGD_SYS_PWROK_OUT: CPLD2.K13(PR7B) R430.1
Q82_G: C479.1 Q82.G R819.1
Q82_S: Q82.S R820.1
RST_PLTRST_BUF_N: R405.1 ; also on sheet 51 78 177
RST_PLTRST_BUF_N_1: CPLD2.E2(PL4A) R405.2
RST_RSMRST_N: CPLD2.J1(PL5D) R642.1 R644.2 ; also on sheet 51 177 182
SMB_HOST_3V3_CLK: DB1.13(SMBCLK) ; also on sheet 161
SMB_HOST_3V3_DATA: DB1.12(SMBDAT) ; also on sheet 161
SMB_HOST_STBY_LVC3_CLK: R543.2 U35.38(SMBCLK) ; also on sheet 47 74 77 90 161
SMB_HOST_STBY_LVC3_DATA: R544.2 U35.39(SMBDAT) ; also on sheet 47 74 77 90 161
SMB_SENSOR_CLK: CPLD2.J13(PR6B) ; also on sheet 74 159 184
SMB_SENSOR_DAT: CPLD2.H13(PR6A) ; also on sheet 74 159 184
TIMER_ALERT_CPLD_N: CPLD2.P11(PB4A) ; also on sheet 61
TP_CKNMG_33M/SMBA: TP439.1 U35.22(33_33MHZ/SMBA)
TP_CLK6_50M_CKMNG: TP300.1 U35.25(RMII6)
TP_CLK7_50M_CKMNG: TP299.1 U35.24(RMII7)
UART_SELECT: R388.2 ; also on sheet 69 180
UART_SELECT_CPLD: CPLD2.A3(PT2F) R388.1
UV_FAN_ALERT_N: CPLD2.P12(PB4C) ; also on sheet 59
UV_FPH_EN: CPLD2.C12(PR2B) R671.2 ; also on sheet 177
VOLTAGE_ALERT_N: R652.2 ; also on sheet 61 177
VOLTAGE_ALERT_N_PLD: CPLD2.B11(PT5B) R652.1
XTAL_IN_MNG: C462.1 U35.19(X1_25) X5.1
XTAL_OUT_MNG: C463.1 U35.20(X2_25) X5.2

Not connected (* = marked no-connect by the designer): CPLD2 A1(PT2B)* A5(PT3B)* A8(PT4B)* A11(PT5A)* A12(PT5C)* B1(PL2A)* B2(PT2A)* B3(PT2E)* C1(PL2B)* C3(PT2C)* D1(PL3B)* D2(PL3A)* D13(PR3D)* D14(PR4A)* E14(PR5A)* F2(PL5A)* J14(PR7A)* M13(PR7D)* N5(PB2C)* N12(PB4D)* N13(PB5D)* P4(PB2A)* P8(PB3B)* P13(PB5A)* P14(PB5C)*; DB1 19(DIF_0)* 20(DIF_0#)* 46(DIF_9)* 47(DIF_9#)* 49(DIF_10)* 50(DIF_10#)* 59(DIF_13)* 60(DIF_13#)* 66(DIF_16)* 67(DIF_16#)* 69(DIF_17)* 70(DIF_17#)*; U24 1(NC#1)*; U35 3(DOT96SST)* 4(DOT96SSC)* 7(CPUCLKT0)* 8(CPUCLKC0)* 17(25MHZ_1)* 28(RMII5)* 29(RMII4)*

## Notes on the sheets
sheet 52
- CPLD FOR LOGIC
- LPC
- 7 segment
- 7 segment
- PCH
- BMC
- CPLD
- DEBUG
- FAB1 20150223
- 0 ohm
- DESIGN NOTE:
  IO PINS C13 & N3 WERE GROUNDED
  TO IMPROVE THE CPLD BREAKOUT
  IO PINS N13 & B2 ARE UNCONNECTED
  TO IMPROVE THE CPLD BREAKOUT
- FAB1 20150212
- FAB1 REV014 20150416
- FAB1 REV007 20150325
- FAB1 REV019 20150421
- FAB1 REV014 20150416
- FAB1 REV002 20150317
- FAB1 REV019 20150421
- FAB1 REV013 20150413
- FAB1 REV004 20150320
- FAB1 REV014 20150416
- FAB1 REV004 20150320
- FAB1 REV002 20150317
- FAB1 REV021 20150424
- FAB1 REV004 20150320
- FAB1 REV019 20150421
- FAB1 REV005 20150320
- FAB1 REV005 20150323
- FAB1 REV001 20150316
- FAB1 REV019 20150421
- FAB1 REV019 20150421
- FAB1 REV003 20150318
- FAB1 REV014 20150416
- Change to 84.27002.N31
- Delete components
sheet 53
- POWER CONNECTOR
- Mated loop output to mid-plane, short between pin D1
  and pin D2 at motherboard; Mid-plane uses this pin to
  detect insertion of motherboard; Need PU at mid-plane.
- FAB1 REV013 20150410
- FAB1 REV019 20150421
- Remove components
sheet 54
- IRQ ALERT
- FAB1 REV002 20150317
- Connect to HSC and BMC
- From MID-PLANE
- From FAST-PROCHOT
- FAB1 REV004 20150320
- FAB1 REV014 20150416
- Change to 84.27002.N31
sheet 55
- CKMNG 202
- Separate 10uF cap and 0.1uF caps 250mil.
  Place 10uF close to bead, and all 0.1uF close to chip pin.
- Place 0.01uF close to chip pin.
- Place 0.01uF close to chip pin.
- 600 ohm @ 100MHz
  DCR 0.1 ohm; 2A
- OE_RMIIB
- Active high input for enabling RMII(7:4) outputs.
  1 = enable output(s),  0 = low
- OE_RMIIA
- Active high input for enabling RMII(3:0) outputs.
  1 = enable output(s),  0 = low
- Layout Note:
  Place serial RES close to CKMNG.
- The total trace length of
  Xtal1 or Xtal2 should be
  less than 750 mils.
- I2C Add = D0 (h)
- Load CAPs need to be as close to the Crystal pads.
sheet 56
- DB1900Z CLOCK TERMINATION (2/2)
- CPU0
- CPU1
- FROM CLK BUFFER
- TO CPU0 QPI CLK
- FROM CLK BUFFER
- TO CPU1 QPI CLK
- FROM CLK BUFFER
- TO CPU0 QPI CLK
- FROM CLK BUFFER
- TO CPU1 QPI CLK
- PCH
- NGFF
- FROM CLK BUFFER
- TO NGFF
- FROM CLK BUFFER
- TO WBG
- LAN
- TO I210
sheet 57
- DB1900Z CLOCK TERMINATION (1/2)
- RISER 1
- RISER 2
- FROM CLK BUFFER
- TO RISER1
- FROM CLK BUFFER
- TO RISER2
- FROM CLK BUFFER
- TO RISER1
- FROM CLK BUFFER
- TO RISER1
- MEZZ
- BMC
- FROM CLK BUFFER
- TO MEZZ1
- FROM CLK BUFFER
- TO MEZZ1
sheet 58
- DB1900Z CLOCK BUFFER
- 71.92190.003
- 600ohm @ 100MHz
  DC resistance 0.3ohm
  Rated current 500mA
- 64.10015.L1L
- OE5:8 - CPU BCLK
- FAB1 REV006 20150324
- OE11:12 - PCIE CLK
- CKPWRGD_PD#
  Notifies device to sample latched inputs
  and start up on first high assertion
- FAB1 REV014 20150416
- Change to 84.27002.N31
- The DB1x00Z/ZL external board feedback
  trace must be routed on the outer (microstrip)
  layer and should be as short as possible
  (< 680 mils).
- SMBUS ADDRESS= 0xD8 - 0xD9
- 64.27R45.6DL
